Omron CX-Programmer project 新工程 (CX-Programmer 4.01)

# PLC 新PLC1: CPM2* 

## Program 新程序1 (no task)

### Section 段1

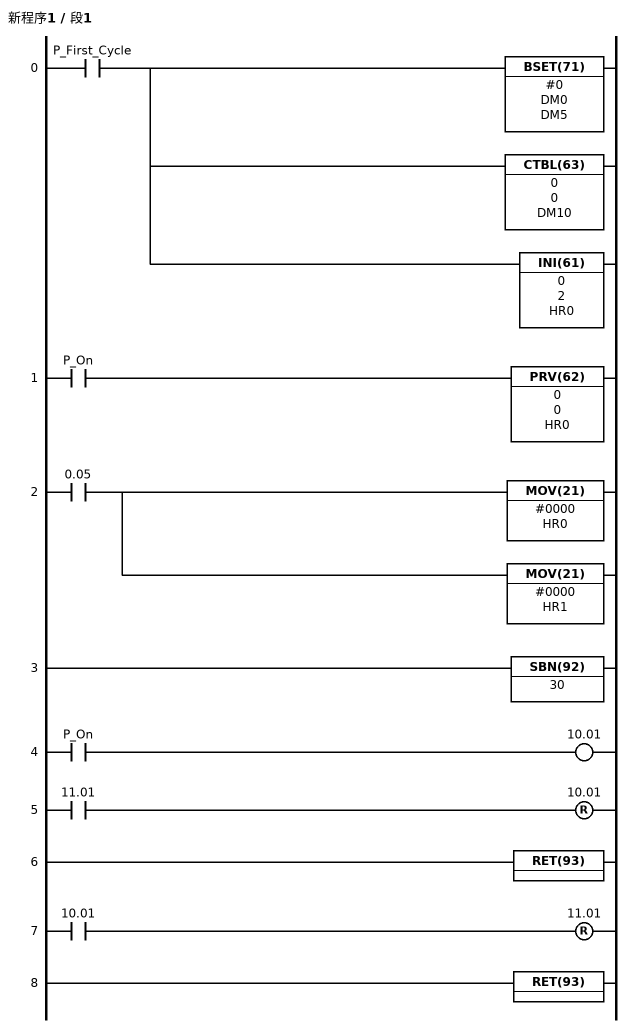
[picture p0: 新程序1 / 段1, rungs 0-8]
; rung 0
LD P_First_Cycle
BSET(71) #0 DM0 DM5
CTBL(63) 0 0 DM10
INI(61) 0 2 HR0
; rung 1
LD P_On
PRV(62) 0 0 HR0
; rung 2
LD 0.05
MOV(21) #0000 HR0
MOV(21) #0000 HR1
; rung 3
SBN(92) 30
; rung 4
LD P_On
OUT 10.01
; rung 5
LD 11.01
RSET 10.01
; rung 6
RET(93)
; rung 7
LD 10.01
RSET 11.01
; rung 8
RET(93)

### Section END
; rung 0
END(01)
